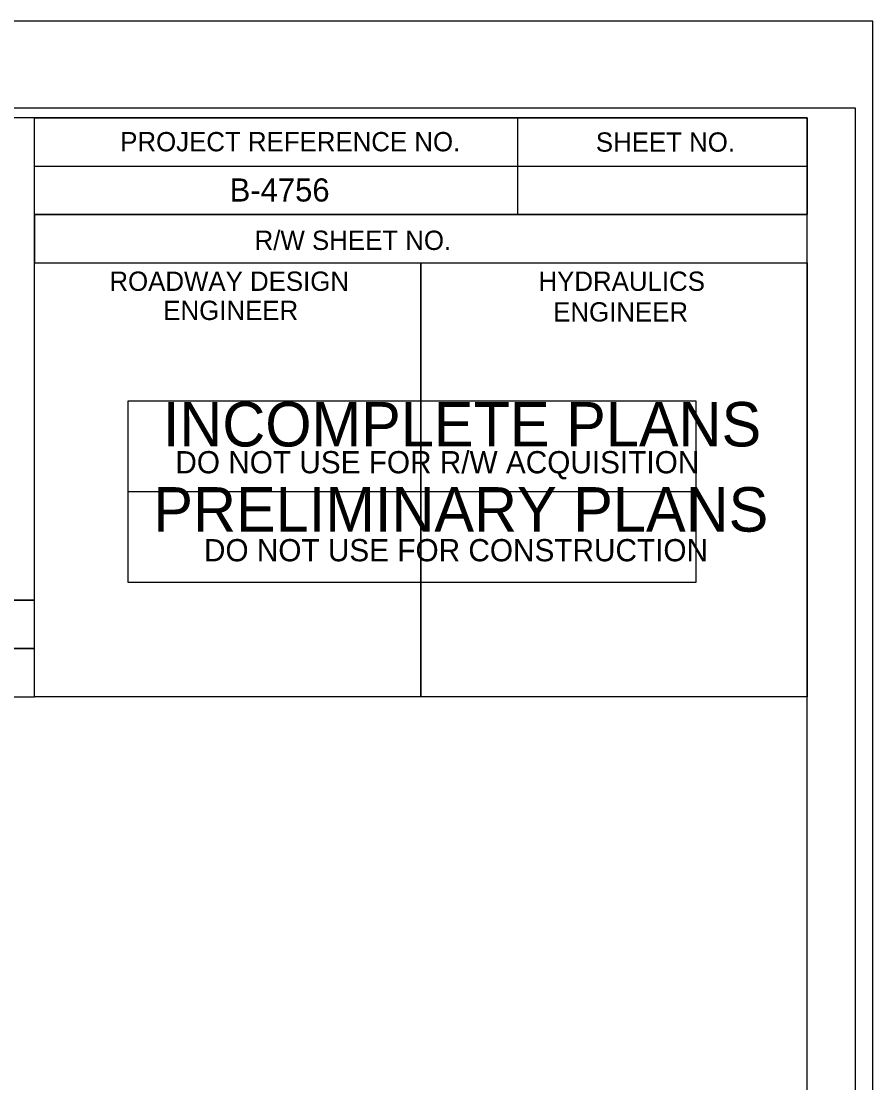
# Model space of a CAD drawing. Extents: x 2431000 to 2534000, y 645879 to 714000.
# Drawn here: x 2467565.7 to 2467786.2, y 672203.6 to 672478.6 of the extents above; entities that cross this region are included whole.
import ezdxf

# ---------------------------------------------------------------- set-up
doc = ezdxf.new("R2010")
doc.units = 0
for name, color, linetype in [('KHA_LOGO', 7, 'Continuous'), ('Sheet Plan CELL', 7, 'Continuous'), ('Sheet Plot Border Inside CELL', 7, 'Continuous'), ('Sheet Plot Border Outside CELL', 7, 'Continuous'), ('Sheet Title CELL', 7, 'Continuous')]:
    doc.layers.add(name, color=color, linetype=linetype)

msp = doc.modelspace()

# ---------------------------------------------------------------- linework, layer by layer
at = {"layer": 'KHA_LOGO'}
for points in [[(2467469.15, 672328.63), (2467569.15, 672328.63), (2467569.15, 672453.63), (2467469.15, 672453.63)], [(2467469.15, 672316.13), (2467569.15, 672316.13), (2467569.15, 672328.63), (2467469.15, 672328.63)], [(2467469.15, 672303.63), (2467569.15, 672303.63), (2467569.15, 672316.13), (2467469.15, 672316.13)]]:
    msp.add_lwpolyline(points, close=True, dxfattribs=at)
at = {"layer": 'Sheet Plan CELL'}
for p, q in [((2467694.2, 672453.58), (2467694.2, 672428.58)), ((2467569.15, 672441.08), (2467769.2, 672441.08)), ((2467569.15, 672428.58), (2467769.2, 672428.58)), ((2467569.15, 672428.58), (2467569.15, 672416.08)), ((2467569.15, 672428.58), (2467769.2, 672428.58)), ((2467669.2, 672416.08), (2467669.2, 672303.63))]:
    msp.add_line(p, q, dxfattribs=at)
for points in [[(2467769.2, 672453.63), (2466269.2, 672453.63), (2466269.2, 671403.63), (2467769.2, 671403.63)], [(2467569.15, 672453.63), (2467769.2, 672453.63), (2467769.2, 672428.58), (2467569.15, 672428.58)], [(2467569.15, 672416.08), (2467669.2, 672416.08), (2467669.2, 672303.58), (2467569.15, 672303.58)], [(2467669.2, 672416.08), (2467769.2, 672416.08), (2467769.2, 672303.58), (2467669.2, 672303.58)]]:
    msp.add_lwpolyline(points, close=True, dxfattribs=at)
at = {"layer": 'Sheet Plot Border Inside CELL'}
msp.add_lwpolyline([(2466115.7, 671401.13), (2467781.7, 671401.13), (2467781.7, 672456.13), (2466115.7, 672456.13)], close=True, dxfattribs=at)
at = {"layer": 'Sheet Plot Border Outside CELL'}
msp.add_lwpolyline([(2466102.7, 671378.63), (2467786.2, 671378.63), (2467786.2, 672478.63), (2466102.7, 672478.63)], close=True, dxfattribs=at)
at = {"layer": 'Sheet Title CELL'}
for points in [[(2467593.43, 672356.76), (2467593.43, 672380.26), (2467740.43, 672380.26), (2467740.43, 672356.77)], [(2467593.43, 672333.27), (2467593.43, 672356.76), (2467740.43, 672356.77), (2467740.43, 672333.27)]]:
    msp.add_lwpolyline(points, close=True, dxfattribs=at)

# ---------------------------------------------------------------- texts
at = {"layer": 'Sheet Plan CELL'}
for s, height, p in [('PROJECT REFERENCE NO.', 5.0001, (2467591.35, 672444.93)), ('SHEET NO.', 5, (2467714.5, 672444.83)), ('B-4756', 6, (2467619.69, 672431.92)), ('R/W SHEET NO.', 5.0001, (2467626.15, 672419.38)), ('ROADWAY DESIGN', 5.0001, (2467588.55, 672408.78)), ('HYDRAULICS', 5, (2467699.65, 672408.78)), ('ENGINEER', 5, (2467602.5, 672401.23)), ('ENGINEER', 5, (2467703.45, 672400.83))]:
    msp.add_text(s, height=height, dxfattribs=at).set_placement(p)
at = {"layer": 'Sheet Title CELL'}
for s, height, p in [('INCOMPLETE PLANS', 11.52, (2467602.38, 672368.47)), ('DO NOT USE FOR R/W ACQUISITION', 5.76, (2467605.63, 672361.51)), ('PRELIMINARY PLANS', 11.52, (2467599.93, 672346.41)), ('DO NOT USE FOR CONSTRUCTION', 5.76, (2467613.03, 672338.72))]:
    msp.add_text(s, height=height, dxfattribs=at).set_placement(p)

doc.saveas('drawing.dxf')
